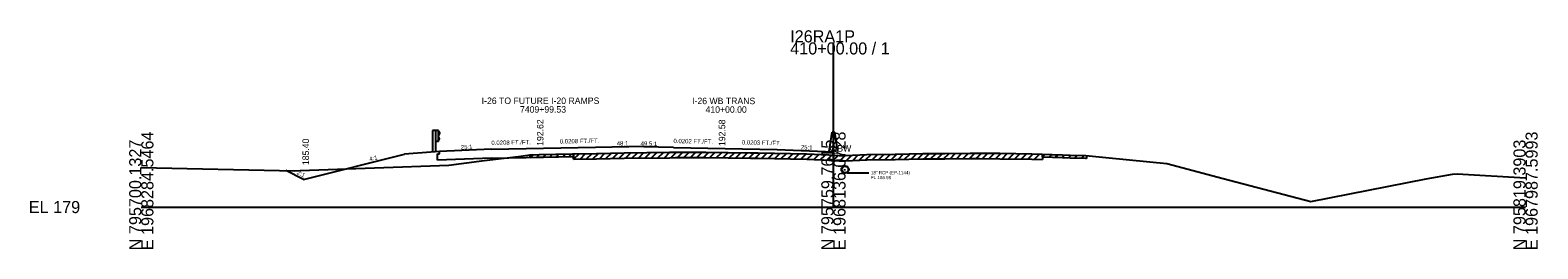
# Model space of a CAD drawing. Extents: x -44 to 4323, y -10 to 9601.
# Drawn here: x -25.7 to 322.8, y 6490.3 to 6541 of the extents above; entities that cross this region are included whole.
import ezdxf

# ---------------------------------------------------------------- set-up
doc = ezdxf.new("R2010")
doc.units = 0
for name, color, linetype in [('1', 7, 'Continuous'), ('DateStamp', 7, 'Continuous'), ('NotForConst', 7, 'Continuous'), ('QCQA', 7, 'Continuous'), ('RD_SHT_Bndy', 7, 'Continuous'), ('RD_SHT_Iplotshp', 7, 'Continuous'), ('RD_SHT_TX', 7, 'Continuous'), ('RD_XS_Base', 7, 'Continuous'), ('RD_XS_ExGround', 7, 'Continuous'), ('RD_XS_Misc_Line', 7, 'Continuous'), ('RD_XS_Pave', 7, 'Continuous'), ('RD_XS_PaveShd', 7, 'Continuous'), ('RD_XS_Pipe', 7, 'Continuous'), ('RD_XS_TX_Elev_PR', 7, 'Continuous'), ('RD_XS_TX_Profile', 7, 'Continuous'), ('RD_XS_TX_ShdSlope', 7, 'Continuous'), ('RD_XS_TX_Slope', 7, 'Continuous'), ('seal', 7, 'Continuous'), ('TR SN EXTRUDED PANEL SIGNS - GROUND MOUNTED', 7, 'Continuous')]:
    doc.layers.add(name, color=color, linetype=linetype)

msp = doc.modelspace()

# ---------------------------------------------------------------- linework, layer by layer
at = {"layer": 'DateStamp'}
msp.add_lwpolyline([(0, 6509.16), (35.47, 6508.4), (36.75, 6508.48), (71.06, 6509.74), (79.25, 6510.76), (87.22, 6511.72), (89.91, 6512.11), (91.97, 6512.15), (99.7, 6512.32), (105.2, 6512.43), (111.64, 6512.56), (122.07, 6512.68), (123.48, 6512.7), (124.06, 6512.7), (130.53, 6512.71), (140.8, 6512.58), (141.72, 6512.57), (142.63, 6512.55), (153.89, 6512.35), (158.93, 6512.08), (159.51, 6512.04), (160, 6512.02), (161.35, 6511.97), (162.18, 6511.95), (162.81, 6511.97), (167.69, 6512.16), (174.26, 6512.28), (180.65, 6512.39), (185.79, 6512.43), (191.63, 6512.48), (193.8, 6512.47), (198.45, 6512.45), (205.87, 6512.35), (212.94, 6512.1), (214.69, 6512.04), (218.35, 6511.92), (223.73, 6511.41), (237.1, 6510.12), (250.11, 6506.63), (270.35, 6501.3), (297, 6506.53), (303.12, 6507.6), (304.21, 6507.7), (320, 6506.76)], dxfattribs=at)
at = {"layer": 'NotForConst'}
for p, q in [((89.91, 6511.49), (90.55, 6512.12)), ((91.41, 6511.52), (92.05, 6512.15)), ((92.91, 6511.55), (93.55, 6512.19)), ((94.41, 6511.58), (95.05, 6512.22)), ((95.91, 6511.61), (96.55, 6512.25)), ((97.41, 6511.65), (98.05, 6512.28)), ((98.92, 6511.68), (99.55, 6512.32)), ((99.92, 6511.07), (101.19, 6512.35)), ((101.42, 6511.1), (102.69, 6512.38)), ((102.92, 6511.13), (104.19, 6512.41)), ((104.42, 6511.16), (105.69, 6512.44)), ((105.92, 6511.19), (107.19, 6512.47)), ((107.42, 6511.22), (108.69, 6512.5)), ((108.92, 6511.25), (110.2, 6512.53)), ((110.42, 6511.28), (111.7, 6512.56)), ((111.92, 6511.31), (113.19, 6512.57)), ((113.42, 6511.33), (114.69, 6512.59)), ((114.92, 6511.34), (116.19, 6512.61)), ((116.42, 6511.36), (117.69, 6512.63)), ((117.93, 6511.38), (119.19, 6512.65)), ((119.43, 6511.4), (120.69, 6512.66)), ((120.93, 6511.42), (122.19, 6512.68)), ((122.43, 6511.43), (123.69, 6512.7)), ((123.93, 6511.45), (125.18, 6512.7)), ((125.43, 6511.45), (126.68, 6512.71)), ((126.93, 6511.46), (128.18, 6512.71)), ((128.43, 6511.46), (129.68, 6512.71)), ((129.93, 6511.46), (131.18, 6512.71)), ((131.43, 6511.45), (132.67, 6512.69)), ((132.93, 6511.43), (134.17, 6512.67)), ((134.43, 6511.42), (135.67, 6512.65)), ((135.93, 6511.4), (137.17, 6512.63)), ((137.44, 6511.38), (138.67, 6512.61)), ((138.94, 6511.36), (140.17, 6512.59)), ((140.44, 6511.34), (141.67, 6512.57)), ((141.94, 6511.32), (143.17, 6512.55)), ((143.44, 6511.29), (144.67, 6512.52)), ((144.94, 6511.26), (146.17, 6512.49)), ((146.44, 6511.23), (147.67, 6512.46)), ((147.94, 6511.21), (149.17, 6512.43)), ((149.44, 6511.18), (150.67, 6512.41)), ((150.94, 6511.15), (152.17, 6512.38)), ((152.44, 6511.12), (153.67, 6512.35)), ((153.94, 6511.09), (155.13, 6512.28)), ((155.44, 6511.01), (156.63, 6512.2)), ((156.95, 6510.93), (158.13, 6512.12)), ((158.45, 6510.85), (159.63, 6512.03)), ((159.95, 6510.77), (161.16, 6511.98)), ((161.45, 6510.72), (162.69, 6511.96)), ((162.95, 6510.72), (164.25, 6512.03)), ((164.45, 6510.78), (165.75, 6512.08)), ((165.95, 6510.84), (167.25, 6512.14)), ((167.45, 6510.9), (168.73, 6512.18)), ((168.95, 6510.93), (170.22, 6512.21)), ((170.45, 6510.96), (171.73, 6512.23)), ((171.95, 6510.99), (173.23, 6512.26)), ((173.45, 6511.01), (174.73, 6512.29)), ((174.95, 6511.04), (176.23, 6512.31)), ((176.46, 6511.07), (177.73, 6512.34)), ((177.96, 6511.09), (179.23, 6512.36)), ((179.46, 6511.12), (180.73, 6512.39)), ((180.96, 6511.14), (182.22, 6512.4)), ((182.46, 6511.15), (183.72, 6512.41)), ((183.96, 6511.17), (185.22, 6512.43)), ((185.46, 6511.18), (186.72, 6512.44)), ((186.96, 6511.19), (188.22, 6512.45)), ((188.46, 6511.2), (189.72, 6512.47)), ((189.96, 6511.22), (191.22, 6512.48)), ((191.46, 6511.23), (192.71, 6512.47)), ((192.96, 6511.22), (194.21, 6512.47)), ((194.46, 6511.21), (195.71, 6512.46)), ((195.97, 6511.21), (197.21, 6512.45)), ((197.47, 6511.2), (198.71, 6512.44)), ((198.97, 6511.19), (200.2, 6512.42)), ((200.47, 6511.17), (201.7, 6512.4)), ((201.97, 6511.15), (203.2, 6512.38)), ((203.47, 6511.13), (204.7, 6512.37)), ((204.97, 6511.11), (206.2, 6512.34)), ((206.47, 6511.08), (207.68, 6512.29)), ((208.34, 6511.64), (208.94, 6512.24)), ((209.84, 6511.58), (210.45, 6512.19)), ((211.34, 6511.53), (211.95, 6512.13)), ((212.84, 6511.48), (213.45, 6512.08)), ((214.34, 6511.42), (214.95, 6512.03)), ((215.84, 6511.38), (216.45, 6511.98)), ((217.35, 6511.33), (217.95, 6511.94))]:
    msp.add_line(p, q, dxfattribs=at)
at = {"layer": 'QCQA'}
for p, q in [((99.92, 6512.32), (105.2, 6512.43)), ((99.92, 6512.32), (99.92, 6511.72)), ((105.2, 6512.43), (111.64, 6512.56)), ((111.64, 6512.56), (122.07, 6512.68)), ((122.07, 6512.68), (123.48, 6512.7)), ((123.48, 6512.7), (124.06, 6512.7)), ((124.06, 6512.7), (130.53, 6512.71)), ((130.53, 6512.71), (140.8, 6512.58)), ((140.8, 6512.58), (141.72, 6512.57)), ((141.72, 6512.57), (142.63, 6512.55)), ((142.63, 6512.55), (153.89, 6512.35)), ((153.89, 6512.35), (158.93, 6512.08)), ((158.93, 6512.08), (159.51, 6512.04)), ((159.51, 6512.04), (160, 6512.02))]:
    msp.add_line(p, q, dxfattribs=at)
at = {"layer": 'RD_SHT_Bndy'}
for p, q in [((160, 6500), (160, 6538.14)), ((0, 6500), (160, 6500)), ((160, 6500), (320, 6500))]:
    msp.add_line(p, q, dxfattribs=at)
at = {"layer": 'RD_SHT_Iplotshp'}
for p, q in [((89.91, 6511.49), (89.91, 6512.11)), ((89.91, 6511.49), (91.97, 6511.53)), ((91.97, 6511.53), (99.7, 6511.69)), ((99.7, 6511.69), (99.92, 6511.7)), ((99.92, 6511.07), (99.92, 6512.32)), ((99.92, 6512.32), (99.92, 6511.7)), ((99.92, 6511.07), (105.2, 6511.18)), ((105.2, 6511.18), (111.64, 6511.31)), ((111.64, 6511.31), (122.07, 6511.43)), ((122.07, 6511.43), (123.48, 6511.45)), ((123.48, 6511.45), (124.06, 6511.45)), ((124.06, 6511.45), (130.53, 6511.46)), ((130.53, 6511.46), (140.8, 6511.33)), ((140.8, 6511.33), (141.72, 6511.32)), ((141.72, 6511.32), (142.63, 6511.3)), ((142.63, 6511.3), (153.89, 6511.1)), ((153.89, 6511.1), (158.93, 6510.83)), ((158.93, 6510.83), (159.51, 6510.79)), ((159.51, 6510.79), (160, 6510.77)), ((160, 6510.77), (161.35, 6510.72)), ((161.35, 6510.72), (162.18, 6510.7)), ((162.18, 6510.7), (162.81, 6510.72)), ((162.81, 6510.72), (167.69, 6510.91)), ((167.69, 6510.91), (174.26, 6511.03)), ((174.26, 6511.03), (180.65, 6511.14)), ((180.65, 6511.14), (185.79, 6511.18)), ((185.79, 6511.18), (191.63, 6511.23)), ((191.63, 6511.23), (193.8, 6511.22)), ((193.8, 6511.22), (198.45, 6511.2)), ((198.45, 6511.2), (205.87, 6511.1)), ((205.87, 6511.1), (208.34, 6511.01)), ((208.34, 6512.26), (208.34, 6511.01)), ((208.34, 6511.64), (208.34, 6512.26)), ((208.34, 6511.64), (212.94, 6511.47)), ((212.94, 6511.47), (214.69, 6511.41)), ((214.69, 6511.41), (218.35, 6511.3)), ((218.35, 6511.3), (218.51, 6511.28)), ((218.51, 6511.91), (218.51, 6511.28))]:
    msp.add_line(p, q, dxfattribs=at)
at = {"layer": 'RD_XS_Base'}
for p, q in [((68.02, 6517.76), (67.35, 6517.76)), ((67.35, 6517.76), (67.35, 6512.7)), ((68.68, 6517.76), (68.02, 6517.76)), ((68.02, 6517.76), (68.02, 6512.81)), ((68.68, 6515.19), (68.68, 6517.76)), ((68.68, 6517.6), (68.95, 6517.16)), ((68.68, 6515.19), (68.02, 6515.19)), ((68.95, 6517.05), (68.68, 6516.61)), ((68.95, 6515.9), (68.68, 6516.34)), ((68.68, 6515.35), (68.95, 6515.79)), ((68.95, 6517.16), (68.95, 6517.05)), ((68.95, 6515.79), (68.95, 6515.9))]:
    msp.add_line(p, q, dxfattribs=at)
at = {"layer": 'RD_XS_Misc_Line'}
for p, q in [((68.45, 6512.31), (68.95, 6512.33)), ((68.45, 6510.83), (68.45, 6512.31)), ((80.96, 6511.33), (68.45, 6510.83)), ((68.95, 6512.33), (68.95, 6512.89)), ((80.96, 6511.33), (92.97, 6511.58)), ((92.97, 6511.58), (99.92, 6511.72))]:
    msp.add_line(p, q, dxfattribs=at)
at = {"layer": 'RD_XS_Pave'}
for p, q in [((37.47, 6506.4), (60.83, 6512.24)), ((66.95, 6512.73), (60.83, 6512.24)), ((37.47, 6506.4), (33.38, 6508.44))]:
    msp.add_line(p, q, dxfattribs=at)
at = {"layer": 'RD_XS_PaveShd'}
msp.add_line((68.95, 6512.89), (66.95, 6512.73), dxfattribs=at)
at = {"layer": 'RD_XS_Pipe'}
msp.add_line((163.18, 6507.96), (168.18, 6507.96), dxfattribs=at)
for radius in [0.85, 0.75]:
    msp.add_circle((162.68, 6508.71), radius, dxfattribs=at)
at = {"layer": 'RD_XS_TX_Elev_PR'}
for p, q in [((80.96, 6513.37), (68.95, 6512.89)), ((104.98, 6513.87), (112.74, 6514.03)), ((123, 6513.82), (112.74, 6514.03)), ((147, 6513.34), (160, 6512.82)), ((160, 6512.82), (160, 6512.02))]:
    msp.add_line(p, q, dxfattribs=at)
at = {"layer": 'RD_XS_TX_ShdSlope'}
for p, q in [((159, 6512.84), (159.67, 6517.32)), ((160, 6517.32), (159.67, 6517.32)), ((160, 6517.32), (160.33, 6517.32)), ((161, 6512.84), (160.33, 6517.32))]:
    msp.add_line(p, q, dxfattribs=at)
at = {"layer": 'RD_XS_TX_Slope'}
for p, q in [((80.96, 6513.37), (92.97, 6513.62)), ((92.97, 6513.62), (104.98, 6513.87)), ((123, 6513.82), (135, 6513.58)), ((135, 6513.58), (147, 6513.34))]:
    msp.add_line(p, q, dxfattribs=at)

# ---------------------------------------------------------------- texts
at = {"layer": '1'}
for s, p in [('I-26 TO FUTURE I-20 RAMPS', (78.69, 6523.87)), ('I-26 WB TRANS', (127.33, 6523.83)), ('7409+99.53', (87.54, 6521.87)), ('410+00.00', (130.43, 6521.83))]:
    msp.add_text(s, height=1.5, dxfattribs=at).set_placement(p)
at = {"layer": 'RD_SHT_Bndy'}
for s, p in [('I26RA1P', (150, 6538.14)), ('410+00.00 / 1', (150, 6535.34)), ('EL 179', (-26, 6498.6))]:
    msp.add_text(s, height=2.8, dxfattribs=at).set_placement(p)
for s, p in [('N 795700.1327', (0, 6490)), ('E 1968284.5464', (2.8, 6490)), ('N 795759.7615', (160, 6490)), ('E 1968136.0728', (162.8, 6490)), ('N 795819.3903', (320, 6490)), ('E 1967987.5993', (322.8, 6490))]:
    msp.add_text(s, height=2.8, rotation=90, dxfattribs=at).set_placement(p)
at = {"layer": 'RD_SHT_TX'}
msp.add_text('191.02', height=1, rotation=90, dxfattribs=at).set_placement((161, 6512.02))
at = {"layer": 'RD_XS_ExGround'}
for s, rotation, p in [('25:1', 2.2892, (73.89, 6513.34)), ('48:1', 1.1924, (109.92, 6514.22)), ('49.5:1', 358.8428, (115.43, 6514.23)), ('25:1', 357.7094, (152.46, 6513.37))]:
    msp.add_text(s, height=1, rotation=rotation, dxfattribs=at).set_placement(p)
at = {"layer": 'RD_XS_Pipe'}
for s, p in [('18" RCP (EP-1144)', (168.68, 6507.59)), ('FL 186.96', (168.68, 6506.46))]:
    msp.add_text(s, height=0.75, dxfattribs=at).set_placement(p)
at = {"layer": 'RD_XS_TX_Profile'}
msp.add_text('WBW', height=1.5, dxfattribs=at).set_placement((159, 6512.84))
at = {"layer": 'seal'}
for s, p in [(' 192.62', (92.97, 6513.62)), (' 192.58', (135, 6513.58)), ('185.40', (38.76, 6509.72))]:
    msp.add_text(s, height=1.5, rotation=90, dxfattribs=at).set_placement(p)
at = {"layer": 'TR SN EXTRUDED PANEL SIGNS - GROUND MOUNTED'}
for s, rotation, p in [('0.0208 FT./FT.', 1.1931, (80.94, 6514.37)), ('0.0208 FT./FT.', 1.1924, (96.76, 6514.7)), ('0.0202 FT./FT.', 358.8428, (123.02, 6514.82)), ('0.0203 FT./FT.', 358.8346, (138.83, 6514.5)), ('4:1', 14.0362, (52.84, 6510.6)), ('2:1', 333.4349, (35.87, 6507.69))]:
    msp.add_text(s, height=1, rotation=rotation, dxfattribs=at).set_placement(p)

doc.saveas('drawing.dxf')
